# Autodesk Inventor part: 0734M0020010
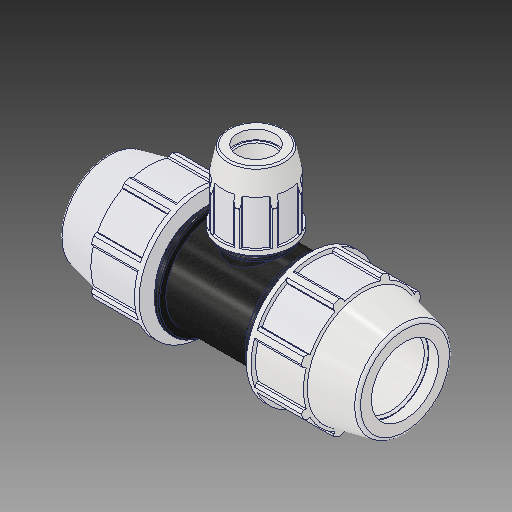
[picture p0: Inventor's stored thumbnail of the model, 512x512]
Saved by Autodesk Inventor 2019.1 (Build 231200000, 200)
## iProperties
Created: 2017-02
Part Number: 0734M0020010
Material: PVC-Piping
Description: PLASSON REDUCING TEE 2'' - 1'' - 2''
Document SubType Name: Modeling
Designer: KIM
Mass: 92.6774 g
Surface Area: 199.44 cm^2
Volume: 66.1981 cm^3
Density: 1.4 g/cm^3
Appearance: PTFE
Author: Кирилл
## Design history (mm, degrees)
derived "0734M0.ipt"
feature "Solid1::0734M0.ipt"
feature "Solid2::0734M0.ipt"
tag "TaggingFeature1"
body "Solid1"
other parameters: "d_" = 60.1, "E_" = 113.03, "A_" = 116.078, "l_" = 112.014, "E_1" = 62.992, "l_1" = 66.04, "d_1" = 33.3, "H_" = 265.938, "d2" = 60.1, "d4" = 11.08075, "d5" = 37.23132, "d7" = 113.03, "d11" = 4.4323, "d13" = 120 deg, "d14" = 84.14, "d15" = 12 deg, "d16" = 98.3361, "d18" = 3.005, "d19" = 35 deg, "d20" = 17.5 deg, "d21" = 105.1179, "d23" = 0, "d25" = 360 deg, "d27" = 2.2606, "d33" = 1.202, "d42" = 47.86884, "d43" = 3.3909, "d46" = 1.803, "d67" = 84.7725, "d76" = 33.3, "d77" = 62.992, "d78" = 12 deg, "d79" = 116.078, "d80" = 120 deg, "d81" = 49.95, "d82" = 9.67317, "d87" = 3.86927, "d89" = 29.0195, "d90" = 34.8234, "d96" = 22.1615, "d98" = 58.58256, "d99" = 35 deg, "d100" = 17.5 deg, "d102" = 0, "d103" = 1.25984, "d107" = 360 deg, "d109" = 0.999, "d112" = 1.665, "d113" = 4.19947, "d114" = 0, "d117" = 265.938, "d118" = 54.80304, "d126" = 54.09, "d127" = 112.014, "d131" = 4.64312, "d132" = 29.97, "d133" = 66.04, "d135" = 0, "d138" = 5.31876, "d143" = 0, "d148" = 47.244, "d168" = 54.09, "d170" = 0, "d171" = 33.3, "d173" = 0, "d176" = 4.19947, "d177" = 0
